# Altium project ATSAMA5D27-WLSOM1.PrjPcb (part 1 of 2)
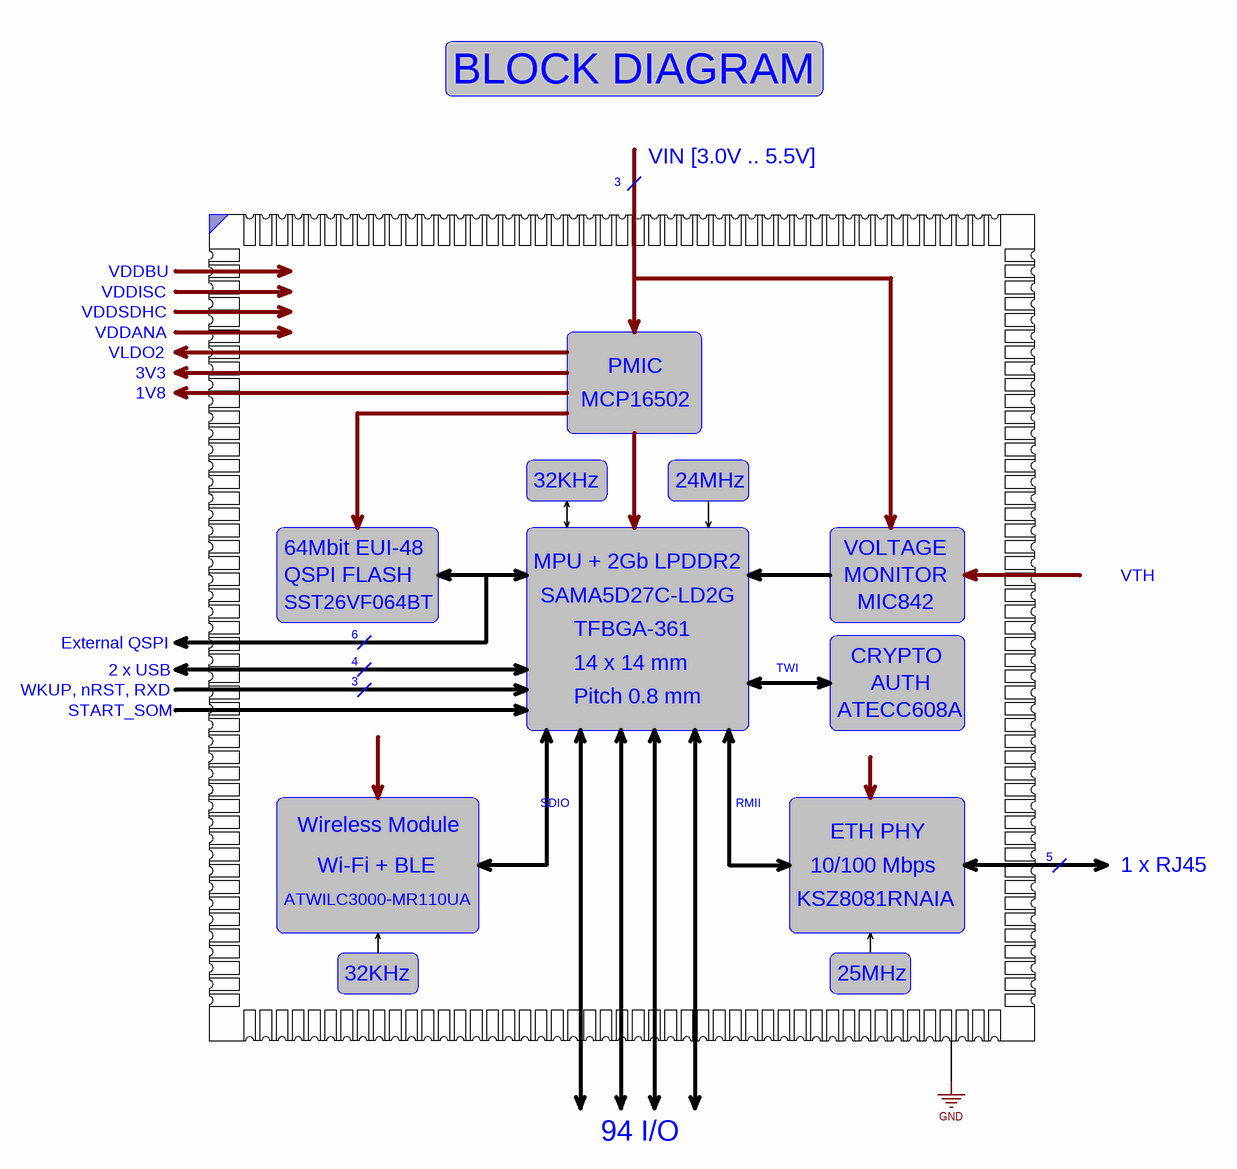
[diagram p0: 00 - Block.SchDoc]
ProjectBoardNumber: WLSOM1; ProjectDrawnBy: MS; ProjectEngineer: RC; ProjectPartNumber: ATSAMA5D27-WLSOM1; ProjectRevisionART: B; ProjectRevisionASSY: B; ProjectRevisionFAB: B; ProjectRevisionSCH: B; ProjectTitle: SAMA5D2 Wireless SOM
6 sheets, 202 parts. Net scope: flat (ports and power ports of the same name join across sheets).
Board file: ATSAMA5D27-WLSOM1.PcbDoc
Sheets:
  00 - Block.SchDoc
  01 - Power.SchDoc
  02 - MPU.SchDoc
  03 - Ethernet.SchDoc
  04 - WiFi-BLE-Flash.SchDoc
  05 - SOM-PIO.SchDoc

## Sheet 00 - Block.SchDoc
size B; CompanyName: Microchip Technology Inc.; Organization: Microchip Technology; Address1: 2355 West Chandler Blvd.; Address2: Chandler, AZ  85224; Address4: USA; SheetNumber: 1; SheetTotal: 6; SheetTitle: BLOCK DIAGRAM

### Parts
(Parts that share a designator on the sheet are numbered #1, #2 ... from top to bottom, then left to right.)
?#1  (no value)  (graphical)

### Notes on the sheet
- BLOCK DIAGRAM
- 3
- VIN [3.0V .. 5.5V]
- VDDBU
- VDDSDHC
- VDDANA
- VDDISC
- VLDO2
- 1V8
- 3V3
- MCP16502
- PMIC
- 32KHz
- 24MHz
- 64Mbit EUI-48
- VOLTAGE
- SST26VF064BT
- QSPI FLASH
- MPU + 2Gb LPDDR2
- SAMA5D27C-LD2G
- TFBGA-361
- MONITOR
- MIC842
- VTH
- WKUP, nRST, RXD
- External QSPI
- 2 x USB
- 4
- 6
- 14 x 14 mm
- TWI
- CRYPTO
- AUTH
- START_SOM
- Pitch 0.8 mm
- ATECC608A
- Wireless Module
- SDIO
- RMII
- ATWILC3000-MR110UA
- Wi-Fi + BLE
- KSZ8081RNAIA
- 10/100 Mbps
- ETH PHY
- 5
- 1 x RJ45
- 25MHz
- 94 I/O
- Labels drawn without touching a wire or pin: GND

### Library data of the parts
?#1 = Title Block B

## Sheet 01 - Power.SchDoc
size B; CompanyName: Microchip Technology Inc.; Organization: Microchip Technology; Address1: 2355 West Chandler Blvd.; Address2: Chandler, AZ  85224; Address4: USA; SheetNumber: 2; SheetTotal: 6; SheetTitle: Power Supply
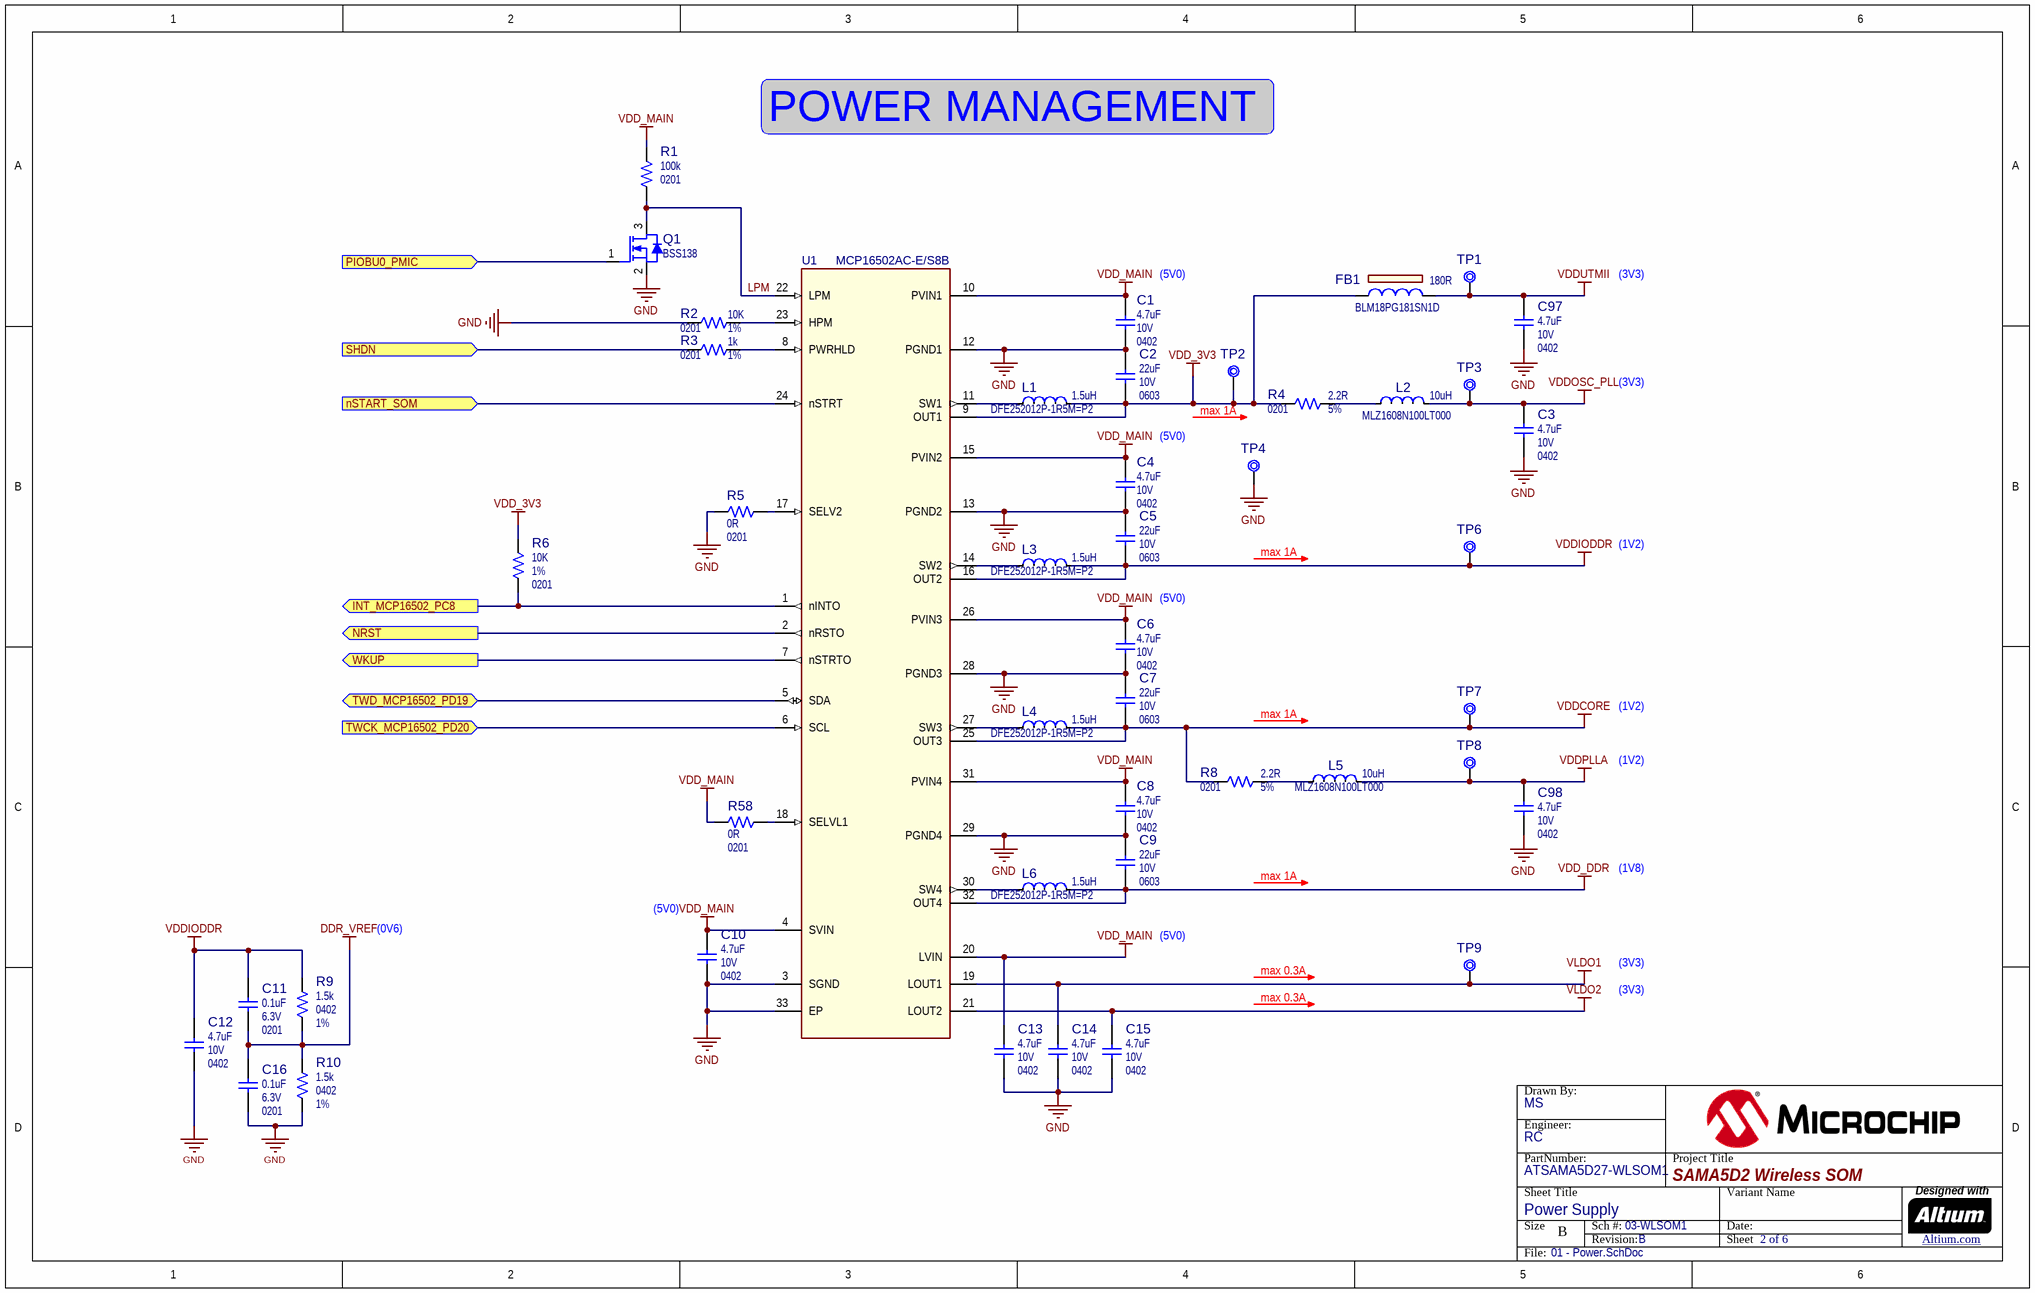
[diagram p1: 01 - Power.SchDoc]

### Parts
(Parts that share a designator on the sheet are numbered #1, #2 ... from top to bottom, then left to right.)
?#2  (no value)  (graphical)
C1  value 4.7uF  Voltage: 10V  Package: 0402  [CAP_C_0402]  (hidden comment: Capacitor NP)
C2  value 22uF  Voltage: 10V  Package: 0603  [CAP_C_0603]  (hidden comment: Capacitor NP)
C3  value 4.7uF  Voltage: 10V  Package: 0402  [CAP_C_0402]  (hidden comment: Capacitor NP)
C4  value 4.7uF  Voltage: 10V  Package: 0402  [CAP_C_0402]  (hidden comment: Capacitor NP)
C5  value 22uF  Voltage: 10V  Package: 0603  [CAP_C_0603]  (hidden comment: Capacitor NP)
C6  value 4.7uF  Voltage: 10V  Package: 0402  [CAP_C_0402]  (hidden comment: Capacitor NP)
C7  value 22uF  Voltage: 10V  Package: 0603  [CAP_C_0603]  (hidden comment: Capacitor NP)
C8  value 4.7uF  Voltage: 10V  Package: 0402  [CAP_C_0402]  (hidden comment: Capacitor NP)
C9  value 22uF  Voltage: 10V  Package: 0603  [CAP_C_0603]  (hidden comment: Capacitor NP)
C10  value 4.7uF  Voltage: 10V  Package: 0402  [CAP_C_0402]  (hidden comment: Capacitor NP)
C11  value 0.1uF  Voltage: 6.3V  Package: 0201  [CAP_C_0201]  (hidden comment: Capacitor NP)
C12  value 4.7uF  Voltage: 10V  Package: 0402  [CAP_C_0402]  (hidden comment: Capacitor NP)
C13  value 4.7uF  Voltage: 10V  Package: 0402  [CAP_C_0402]  (hidden comment: Capacitor NP)
C14  value 4.7uF  Voltage: 10V  Package: 0402  [CAP_C_0402]  (hidden comment: Capacitor NP)
C15  value 4.7uF  Voltage: 10V  Package: 0402  [CAP_C_0402]  (hidden comment: Capacitor NP)
C16  value 0.1uF  Voltage: 6.3V  Package: 0201  [CAP_C_0201]  (hidden comment: Capacitor NP)
C97  value 4.7uF  Voltage: 10V  Package: 0402  [CAP_C_0402]  (hidden comment: Capacitor NP)
C98  value 4.7uF  Voltage: 10V  Package: 0402  [CAP_C_0402]  (hidden comment: Capacitor NP)
FB1  value 180R  Manufacturer Part Number 1: BLM18PG181SN1D  [IND_C_0603]  (hidden comment: Ferrite Bead)
L1  value 1.5uH  Manufacturer Part Number 1: DFE252012P-1R5M=P2  [IND_C_1008]  (hidden comment: Inductor)
L2  value 10uH  Manufacturer Part Number 1: MLZ1608N100LT000  [IND_C_0603]  (hidden comment: Inductor)
L3  value 1.5uH  Manufacturer Part Number 1: DFE252012P-1R5M=P2  [IND_C_1008]  (hidden comment: Inductor)
L4  value 1.5uH  Manufacturer Part Number 1: DFE252012P-1R5M=P2  [IND_C_1008]  (hidden comment: Inductor)
L5  value 10uH  Manufacturer Part Number 1: MLZ1608N100LT000  [IND_C_0603]  (hidden comment: Inductor)
L6  value 1.5uH  Manufacturer Part Number 1: DFE252012P-1R5M=P2  [IND_C_1008]  (hidden comment: Inductor)
Q1  value BSS138  [SOT-23-3]  (hidden comment: Transistor MOS-N GSD)
R1  value 100k  Package: 0201  [RES_C_0201]  (hidden comment: Resistor)
R2  value 10K  Package: 0201  Tolerance: 1%  [RES_C_0201]  (hidden comment: Resistor)
R3  value 1k  Package: 0201  Tolerance: 1%  [RES_C_0201]  (hidden comment: Resistor)
R4  value 2.2R  Package: 0201  Tolerance: 5%  [RES_C_0201]  (hidden comment: Resistor)
R5  value 0R  Package: 0201  [RES_C_0201]  (hidden comment: Resistor)
R6  value 10K  Package: 0201  Tolerance: 1%  [RES_C_0201]  (hidden comment: Resistor)
R8  value 2.2R  Package: 0201  Tolerance: 5%  [RES_C_0201]  (hidden comment: Resistor)
R9  value 1.5k  Package: 0402  Tolerance: 1%  [RES_C_0402]  (hidden comment: Resistor)
R10  value 1.5k  Package: 0402  Tolerance: 1%  [RES_C_0402]  (hidden comment: Resistor)
R58  value 0R  Package: 0201  [RES_C_0201_NT]  (hidden comment: Resistor)  (net tie, no BOM)
TP1  Test Point No BOM  [TP_1mm_SMD]  (value not drawn)  (no BOM)
TP2  Test Point No BOM  [TP_1mm_SMD]  (value not drawn)  (no BOM)
TP3  Test Point No BOM  [TP_1mm_SMD]  (value not drawn)  (no BOM)
TP4  Test Point No BOM  [TP_1mm_SMD]  (value not drawn)  (no BOM)
TP6  Test Point No BOM  [TP_1mm_SMD]  (value not drawn)  (no BOM)
TP7  Test Point No BOM  [TP_1mm_SMD]  (value not drawn)  (no BOM)
TP8  Test Point No BOM  [TP_1mm_SMD]  (value not drawn)  (no BOM)
TP9  Test Point No BOM  [TP_1mm_SMD]  (value not drawn)  (no BOM)
U1  value MCP16502AC-E/S8B  [QFN-32_5X5_EP3.7X3.7]  (hidden comment: MCP16502 QFN-32)

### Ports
INT_MCP16502_PC8 (out), NRST (out), nSTART_SOM (in), PIOBU0_PMIC (in), SHDN (in), TWCK_MCP16502_PD20 (in), TWD_MCP16502_PD19 (bidir), WKUP (out)

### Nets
DDR_VREF: C11.1 C16.2 R9.1 R10.2
GND: C1.1 C2.2 C3.1 C4.1 C5.2 C6.1 C7.2 C8.1 C9.2 C10.1 C12.1 C13.1 C14.1 C15.1 C16.1 C97.1 C98.1 Q1.2(S) R2.2 R5.2 R10.1 TP4.1 U1.3(SGND) U1.12(PGND1) U1.13(PGND2) U1.28(PGND3) U1.29(PGND4) U1.33(EP)
VDD_3V3: C2.1 FB1.1 L1.2(F) R4.1 R6.2 TP2.1 U1.9(OUT1)
VDD_DDR: C9.1 L6.2(F) U1.32(OUT4)
VDD_MAIN: C1.2 C4.2 C6.2 C8.2 C10.2 C13.2 R1.2 R58.1 U1.4(SVIN) U1.10(PVIN1) U1.15(PVIN2) U1.20(LVIN) U1.26(PVIN3) U1.31(PVIN4)
VDDCORE: C7.1 L4.2(F) R8.1 TP7.1 U1.25(OUT3)
VDDIODDR: C5.1 C11.2 C12.2 L3.2(F) R9.2 TP6.1 U1.16(OUT2)
VDDOSC_PLL: C3.2 L2.2(F) TP3.1
VDDPLLA: C98.2 L5.2(F) TP8.1
VDDUTMII: C97.2 FB1.2 TP1.1
VLDO1: C14.2 TP9.1 U1.19(LOUT1)
VLDO2: C15.2 U1.21(LOUT2)
INT_MCP16502_PC8: R6.1 U1.1(nINTO) ; port INT_MCP16502_PC8
LPM: Q1.3(D) R1.1 U1.22(LPM)
NRST: U1.2(nRSTO) ; port NRST
nSTART_SOM: U1.24(nSTRT) ; port nSTART_SOM
PIOBU0_PMIC: Q1.1(G) ; port PIOBU0_PMIC
SHDN: R3.1 ; port SHDN
TWCK_MCP16502_PD20: U1.6(SCL) ; port TWCK_MCP16502_PD20
TWD_MCP16502_PD19: U1.5(SDA) ; port TWD_MCP16502_PD19
WKUP: U1.7(nSTRTO) ; port WKUP
NetL1_1: L1.1(S) U1.11(SW1)
NetL2_1: L2.1(S) R4.2
NetL3_1: L3.1(S) U1.14(SW2)
NetL4_1: L4.1(S) U1.27(SW3)
NetL5_1: L5.1(S) R8.2
NetL6_1: L6.1(S) U1.30(SW4)
NetR2_1: R2.1 U1.23(HPM)
NetR3_2: R3.2 U1.8(PWRHLD)
NetR5_1: R5.1 U1.17(SELV2)
NetR58_2: R58.2 U1.18(SELVL1)

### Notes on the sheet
- POWER MANAGEMENT
- (near C1) (5V0)
- (3V3)
- (near TP2) max 1A
- (5V0)
- max 1A
- (1V2)
- (near C10) (5V0)
- (1V8)
- (0V6)
- max 0.3A

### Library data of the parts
?#2 = Title Block B
C1 C3 C4 C6 C8 C10 C12-C15 C97 C98 = CAP1684: Capacitor; Manufacturer 1: TDK Corporation; Manufacturer Part Number 1: C1005X5R1A475K050BC; Description_: CAP CER 4.7uF 10V 10% X5R SMD 0402; Dev Tools Status: Production; Tolerance: 10%; Temperature Coeffcient: X5R; Type: Ceramic; Owner: Jesus Aviles; Populated: YES
C2 C5 C7 C9 = CAP1648: Capacitor; Manufacturer 1: TDK Corporation; Manufacturer Part Number 1: C1608X5R1A226M080AC; Description_: CAP CER 22uF 10V 20% X5R SMD 0603; Dev Tools Status: Production; Tolerance: 20%; Temperature Coeffcient: X5R; Type: Ceramic; Owner: Razvan Cristescu; Populated: YES
C11 C16 = CAP2003: Capacitor; Manufacturer 1: KEMET; Manufacturer Part Number 1: C0201C104K9PACTU; Description_: CAP CER 0.1uF 6.3V 10% X5R 0201; Dev Tools Status: Design; Tolerance: 10%; Temperature Coeffcient: X5R; Owner: Dragos Danaila; Populated: YES; ESR: 0.005R; Type: Ceramic
FB1 = IND1453: FERRITE 180R 1.5A SMD 0603; Manufacturer 1: Murata Electronics North America; Dev Tools Status: Production; Owner: Dragos Danaila; DCR: 0.09R; Test Frequency: 100MHz; Populated: YES
L1 L3 L4 L6 = IND1335: Manufacturer 1: Murata Electronics North America; Description_: INDUCTOR 1.5uH 3.5A 20% SMD 1008; Dev Tools Status: Design; Owner: Razvan Cristescu; DCR: 0.06R; RMS Current: 3.5A; Test Frequency: 1MHz; Populated: YES
L2 L5 = IND1213: Manufacturer 1: TDK Corporation; Description_: INDUCTOR 10uH 600mA 20% SMD 0603; Dev Tools Status: Design; Owner: Jamus Griego; Populated: YES; DCR: 0.6R; RMS Current: 300mA; Saturation Current: 60mA; Test Frequency: 2MHz
Q1 = TRA1147: Transistor MOS; Manufacturer 1: Fairchild; Description_: TRANS FET N-CH BSS138 50V 220mA 360mW SOT-23; Dev Tools Status: Production; Type: FET; Current: 220mA; Drain to Source Voltage: 50V; Gate to Source Voltage: 1.3V; Power: 360mW; Owner: Razvan Cristescu; Populated: YES
R1 = RES1582: Manufacturer 1: Panasonic Electronic Components; Manufacturer Part Number 1: ERJ-1GEF1003C; Tolerance: 1%; Description_: RES TKF 100k 1% 1/20W SMD 0201; Dev Tools Status: Design; Voltage: 15V; Temperature Coeffcient: 200ppm/C; Power: 1/20W; Owner: Gabor Bihari; Populated: YES
R2 R6 = RSMT1252: Manufacturer 1: Yageo; Manufacturer Part Number 1: RC0201FR-0710KL; Description_: RES TKF 10K 1% 1/20W SMD 0201; Dev Tools Status: Design; Voltage: 25V; Temperature Coeffcient: 200pm/C; Power: 1/20W; Owner: Dragos Danaila; Populated: YES
R3 = RES1588: Manufacturer 1: Panasonic Electronic Components; Manufacturer Part Number 1: ERJ-1GEF1001C; Description_: RES TKF 1k 1% 1/20W SMD 0201; Dev Tools Status: Design; Voltage: 25V; Power: 1/20W; Owner: Gabor Bihari; Populated: YES
R4 R8 = RSMT1253: Manufacturer 1: Yageo; Manufacturer Part Number 1: RC0201JR-072R2L; Description_: RES TKF 2.2R 5% 1/20W SMD 0201; Dev Tools Status: Design; Voltage: 25V; Temperature Coeffcient: -100/+350 ppm/C; Power: 1/20W; Owner: Dragos Danaila; Populated: YES
R5 = RSMT1240: Manufacturer 1: Panasonic Electronic Components; Manufacturer Part Number 1: ERJ-1GN0R00C; Description_: RES TKF 0R 1/20W SMD 0201; Dev Tools Status: Design; Voltage: 50V; Current: 0.5A; Power: 1/20W; Owner: Dragos Danaila; Populated: YES
R9 R10 = RES2022: Manufacturer 1: Yageo; Manufacturer Part Number 1: RC0402FR-071K5L; Description_: RES TKF 1.5K 1% 1/16W SMD 0402; Dev Tools Status: Design; Temperature Coeffcient: 100ppm/°C; Power: 1/16W; Owner: Ilie Galan; Populated: YES
R58 = RSMT1240: Manufacturer 1: Panasonic Electronic Components; Manufacturer Part Number 1: ERJ-1GN0R00C; Description_: RES TKF 0R 1/20W SMD 0201; Dev Tools Status: Design; Voltage: 50V; Current: 0.5A; Power: 1/20W; Owner: Dragos Danaila; Populated: DNP
TP1-TP4 TP6-TP9 = CON1759: Test Point; Value: TP PAD PCB 1mm; Description_: CON TP PAD PCB 1mm SMD; Dev Tools Status: Design; Owner: Cristian Papuc; Populated: YES
U1 = MIC8644: Manufacturer 1: Microchip Technology; Description_: MCHP ANALOG PMIC SWITCHER Buck ADJ MCP16502AC-E/S8B QFN-32; Dev Tools Status: Design; Owner: Dragos Danaila; Populated: YES

## Sheet 02 - MPU.SchDoc
size A3; CompanyName: Microchip Technology Inc.; Organization: Microchip Technology; Address1: 2355 West Chandler Blvd.; Address2: Chandler, AZ  85224; Address4: USA; SheetNumber: 3; SheetTotal: 6; SheetTitle: SAMA5D2-LPDDR2-SIP
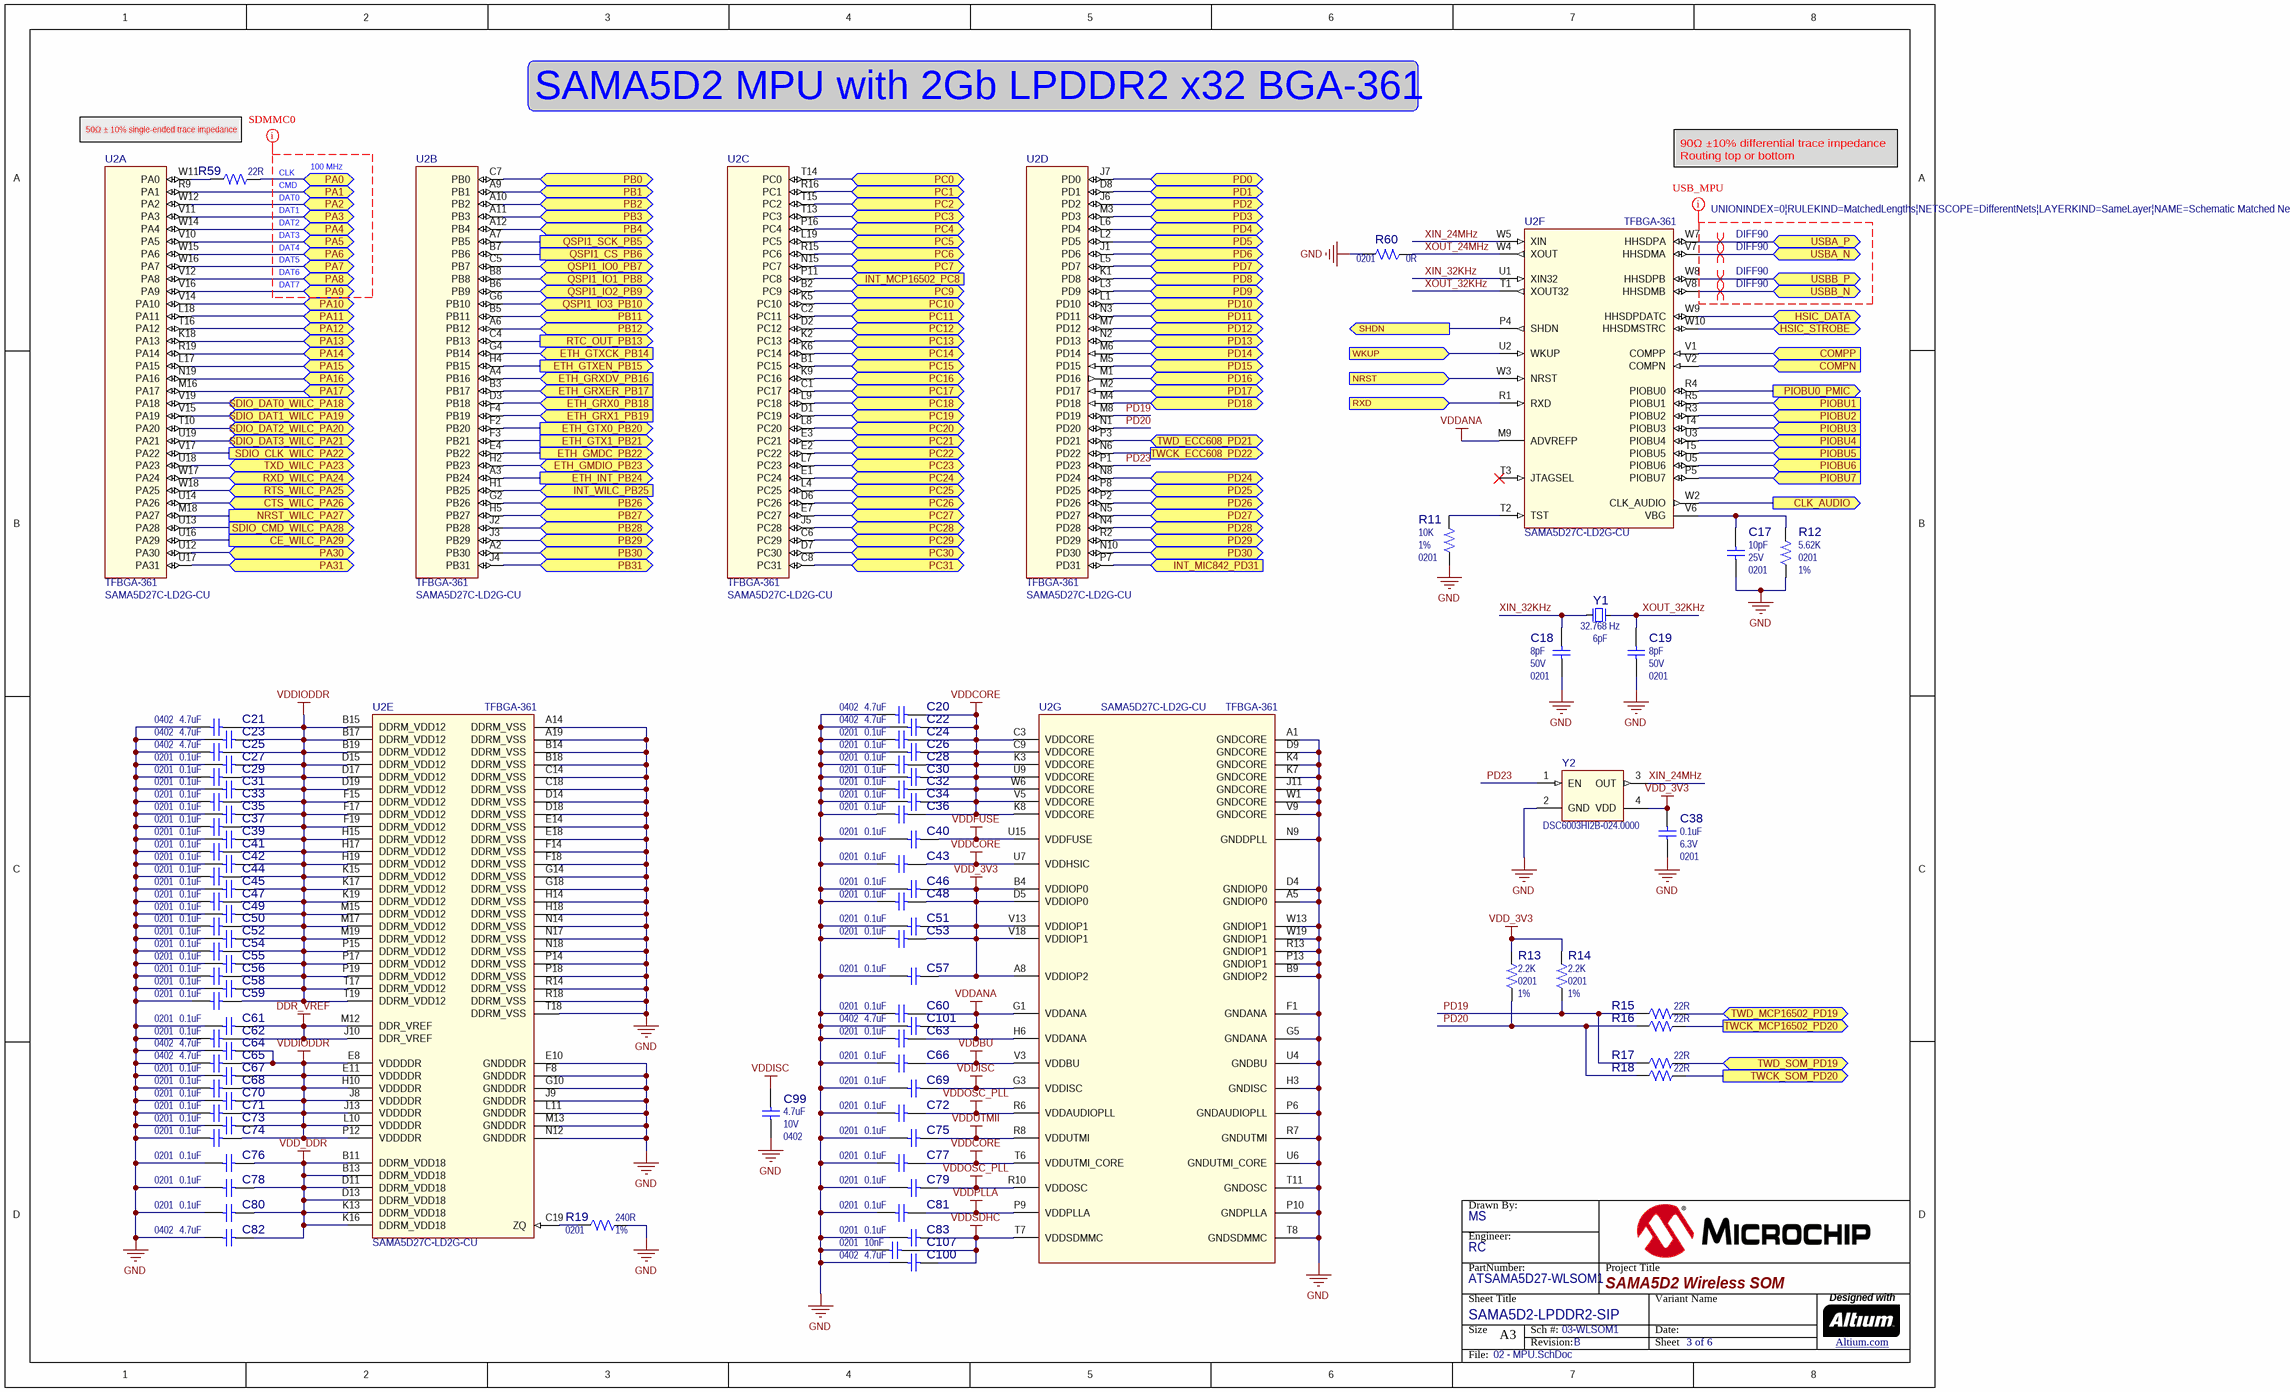
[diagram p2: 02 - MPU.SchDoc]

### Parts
(Parts that share a designator on the sheet are numbered #1, #2 ... from top to bottom, then left to right.)
?#3  (no value)  (graphical)
C17  value 10pF  Voltage: 25V  Package: 0201  [CAP_C_0201]  (hidden comment: Capacitor NP)
C18  value 8pF  Voltage: 50V  Package: 0201  [CAP_C_0201]  (hidden comment: Capacitor NP)
C19  value 8pF  Voltage: 50V  Package: 0201  [CAP_C_0201]  (hidden comment: Capacitor NP)
C20  value 4.7uF  Package: 0402  [CAP_C_0402]  (hidden comment: Capacitor NP)
C21  value 4.7uF  Package: 0402  [CAP_C_0402]  (hidden comment: Capacitor NP)
C22  value 4.7uF  Package: 0402  [CAP_C_0402]  (hidden comment: Capacitor NP)
C23  value 4.7uF  Package: 0402  [CAP_C_0402]  (hidden comment: Capacitor NP)
C24  value 0.1uF  Package: 0201  [CAP_C_0201]  (hidden comment: Capacitor NP)
C25  value 4.7uF  Package: 0402  [CAP_C_0402]  (hidden comment: Capacitor NP)
C26  value 0.1uF  Package: 0201  [CAP_C_0201]  (hidden comment: Capacitor NP)
C27  value 0.1uF  Package: 0201  [CAP_C_0201]  (hidden comment: Capacitor NP)
C28  value 0.1uF  Package: 0201  [CAP_C_0201]  (hidden comment: Capacitor NP)
C29  value 0.1uF  Package: 0201  [CAP_C_0201]  (hidden comment: Capacitor NP)
C30  value 0.1uF  Package: 0201  [CAP_C_0201]  (hidden comment: Capacitor NP)
C31  value 0.1uF  Package: 0201  [CAP_C_0201]  (hidden comment: Capacitor NP)
C32  value 0.1uF  Package: 0201  [CAP_C_0201]  (hidden comment: Capacitor NP)
C33  value 0.1uF  Package: 0201  [CAP_C_0201]  (hidden comment: Capacitor NP)
C34  value 0.1uF  Package: 0201  [CAP_C_0201]  (hidden comment: Capacitor NP)
C35  value 0.1uF  Package: 0201  [CAP_C_0201]  (hidden comment: Capacitor NP)
C36  value 0.1uF  Package: 0201  [CAP_C_0201]  (hidden comment: Capacitor NP)
C37  value 0.1uF  Package: 0201  [CAP_C_0201]  (hidden comment: Capacitor NP)
C38  value 0.1uF  Voltage: 6.3V  Package: 0201  [CAP_C_0201]  (hidden comment: Capacitor NP)
C39  value 0.1uF  Package: 0201  [CAP_C_0201]  (hidden comment: Capacitor NP)
C40  value 0.1uF  Package: 0201  [CAP_C_0201]  (hidden comment: Capacitor NP)
C41  value 0.1uF  Package: 0201  [CAP_C_0201]  (hidden comment: Capacitor NP)
C42  value 0.1uF  Package: 0201  [CAP_C_0201]  (hidden comment: Capacitor NP)
C43  value 0.1uF  Package: 0201  [CAP_C_0201]  (hidden comment: Capacitor NP)
C44  value 0.1uF  Package: 0201  [CAP_C_0201]  (hidden comment: Capacitor NP)
C45  value 0.1uF  Package: 0201  [CAP_C_0201]  (hidden comment: Capacitor NP)
C46  value 0.1uF  Package: 0201  [CAP_C_0201]  (hidden comment: Capacitor NP)
C47  value 0.1uF  Package: 0201  [CAP_C_0201]  (hidden comment: Capacitor NP)
C48  value 0.1uF  Package: 0201  [CAP_C_0201]  (hidden comment: Capacitor NP)
C49  value 0.1uF  Package: 0201  [CAP_C_0201]  (hidden comment: Capacitor NP)
C50  value 0.1uF  Package: 0201  [CAP_C_0201]  (hidden comment: Capacitor NP)
C51  value 0.1uF  Package: 0201  [CAP_C_0201]  (hidden comment: Capacitor NP)
C52  value 0.1uF  Package: 0201  [CAP_C_0201]  (hidden comment: Capacitor NP)
C53  value 0.1uF  Package: 0201  [CAP_C_0201]  (hidden comment: Capacitor NP)
C54  value 0.1uF  Package: 0201  [CAP_C_0201]  (hidden comment: Capacitor NP)
C55  value 0.1uF  Package: 0201  [CAP_C_0201]  (hidden comment: Capacitor NP)
C56  value 0.1uF  Package: 0201  [CAP_C_0201]  (hidden comment: Capacitor NP)
C57  value 0.1uF  Package: 0201  [CAP_C_0201]  (hidden comment: Capacitor NP)
C58  value 0.1uF  Package: 0201  [CAP_C_0201]  (hidden comment: Capacitor NP)
C59  value 0.1uF  Package: 0201  [CAP_C_0201]  (hidden comment: Capacitor NP)
C60  value 0.1uF  Package: 0201  [CAP_C_0201]  (hidden comment: Capacitor NP)
C61  value 0.1uF  Package: 0201  [CAP_C_0201]  (hidden comment: Capacitor NP)
C62  value 0.1uF  Package: 0201  [CAP_C_0201]  (hidden comment: Capacitor NP)
C63  value 0.1uF  Package: 0201  [CAP_C_0201]  (hidden comment: Capacitor NP)
C64  value 4.7uF  Package: 0402  [CAP_C_0402]  (hidden comment: Capacitor NP)
C65  value 4.7uF  Package: 0402  [CAP_C_0402]  (hidden comment: Capacitor NP)
C66  value 0.1uF  Package: 0201  [CAP_C_0201]  (hidden comment: Capacitor NP)
C67  value 0.1uF  Package: 0201  [CAP_C_0201]  (hidden comment: Capacitor NP)
C68  value 0.1uF  Package: 0201  [CAP_C_0201]  (hidden comment: Capacitor NP)
C69  value 0.1uF  Package: 0201  [CAP_C_0201]  (hidden comment: Capacitor NP)
C70  value 0.1uF  Package: 0201  [CAP_C_0201]  (hidden comment: Capacitor NP)
C71  value 0.1uF  Package: 0201  [CAP_C_0201]  (hidden comment: Capacitor NP)
C72  value 0.1uF  Package: 0201  [CAP_C_0201]  (hidden comment: Capacitor NP)
C73  value 0.1uF  Package: 0201  [CAP_C_0201]  (hidden comment: Capacitor NP)
C74  value 0.1uF  Package: 0201  [CAP_C_0201]  (hidden comment: Capacitor NP)
C75  value 0.1uF  Package: 0201  [CAP_C_0201]  (hidden comment: Capacitor NP)
C76  value 0.1uF  Package: 0201  [CAP_C_0201]  (hidden comment: Capacitor NP)
C77  value 0.1uF  Package: 0201  [CAP_C_0201]  (hidden comment: Capacitor NP)
C78  value 0.1uF  Package: 0201  [CAP_C_0201]  (hidden comment: Capacitor NP)
C79  value 0.1uF  Package: 0201  [CAP_C_0201]  (hidden comment: Capacitor NP)
C80  value 0.1uF  Package: 0201  [CAP_C_0201]  (hidden comment: Capacitor NP)
C81  value 0.1uF  Package: 0201  [CAP_C_0201]  (hidden comment: Capacitor NP)
C82  value 4.7uF  Package: 0402  [CAP_C_0402]  (hidden comment: Capacitor NP)
C83  value 0.1uF  Package: 0201  [CAP_C_0201]  (hidden comment: Capacitor NP)
C99  value 4.7uF  Voltage: 10V  Package: 0402  [CAP_C_0402]  (hidden comment: Capacitor NP)
C100  value 4.7uF  Package: 0402  [CAP_C_0402]  (hidden comment: Capacitor NP)
C101  value 4.7uF  Package: 0402  [CAP_C_0402]  (hidden comment: Capacitor NP)
C107  value 10nF  Package: 0201  [CAP_C_0201]  (hidden comment: Capacitor NP)
R11  value 10K  Package: 0201  Tolerance: 1%  [RES_C_0201]  (hidden comment: Resistor)
R12  value 5.62K  Package: 0201  Tolerance: 1%  [RES_C_0201]  (hidden comment: Resistor)
R13  value 2.2K  Package: 0201  Tolerance: 1%  [RES_C_0201]  (hidden comment: Resistor)
R14  value 2.2K  Package: 0201  Tolerance: 1%  [RES_C_0201]  (hidden comment: Resistor)
R15  value 22R  [RES_C_0201]  (hidden comment: Resistor)
R16  value 22R  [RES_C_0201]  (hidden comment: Resistor)
R17  value 22R  [RES_C_0201]  (hidden comment: Resistor)
R18  value 22R  [RES_C_0201]  (hidden comment: Resistor)
R19  value 240R  Package: 0201  Tolerance: 1%  [RES_C_0201]  (hidden comment: Resistor)
R59  value 22R  [RES_C_0201]  (hidden comment: Resistor)
R60  value 0R  Package: 0201  [RES_C_0201]  (hidden comment: Resistor)
U2  SAMA5D27C-LD2G-CU  PackageType: TFBGA-361  [TFBGA-361-16X16]  (parts A,B,C,D,E,F,G of 7)
Y1  value 32.768 Hz  Load Capacitance: 6pF  [CRYSTAL_NX2012SA]  (hidden comment: Crystal 2 Pins)
Y2  Manufacturer Part Number 1: DSC6003HI2B-024.0000  [DFN-4_VFLGA_1.6 X 1.2]  (hidden comment: OSCILLATOR 4 Pins)

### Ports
CE_WILC_PA29 (out), CLK_AUDIO (out), COMPN (in), COMPP (in), CTS_WILC_PA26 (bidir), ETH_GMDC_PB22 (out), ETH_GMDIO_PB23 (bidir), ETH_GRX0_PB18 (in), ETH_GRX1_PB19 (in), ETH_GRXDV_PB16 (in), ETH_GRXER_PB17 (in), ETH_GTX0_PB20 (out), ETH_GTX1_PB21 (out), ETH_GTXCK_PB14 (in), ETH_GTXEN_PB15 (out), ETH_INT_PB24 (out), HSIC_DATA (bidir), HSIC_STROBE (bidir), INT_MCP16502_PC8 (in), INT_MIC842_PD31 (in), INT_WILC_PB25 (in), NRST (in), NRST_WILC_PA27 (out), PA0 (bidir), PA1 (bidir), PA2 (bidir), PA3 (bidir), PA4 (bidir), PA5 (bidir), PA6 (bidir), PA7 (bidir), PA8 (bidir), PA9 (bidir), PA10 (bidir), PA11 (bidir), PA12 (bidir), PA13 (bidir), PA14 (bidir), PA15 (bidir), PA16 (bidir), PA17 (bidir), PA30 (bidir), PA31 (bidir), PB0 (bidir), PB1 (bidir), PB2 (bidir), PB3 (bidir), PB4 (bidir), PB11 (bidir), PB12 (bidir), PB26 (bidir), PB27 (bidir), PB28 (bidir), PB29 (bidir), PB30 (bidir), PB31 (bidir), PC0 (bidir), PC1 (bidir), PC2 (bidir), PC3 (bidir), PC4 (bidir), PC5 (bidir), PC6 (bidir), PC7 (bidir), PC9 (bidir), PC10 (bidir), PC11 (bidir), PC12 (bidir), PC13 (bidir), PC14 (bidir), PC15 (bidir), PC16 (bidir), PC17 (bidir), PC18 (bidir), PC19 (bidir), PC20 (bidir), PC21 (bidir), PC22 (bidir), PC23 (bidir), PC24 (bidir), PC25 (bidir), PC26 (bidir), PC27 (bidir), PC28 (bidir), PC29 (bidir), PC30 (bidir), PC31 (bidir), PD0 (bidir), PD1 (bidir), PD2 (bidir), PD3 (bidir), PD4 (bidir), PD5 (bidir), PD6 (bidir), PD7 (bidir), PD8 (bidir), PD9 (bidir), PD10 (bidir), PD11 (bidir), PD12 (bidir), PD13 (bidir), PD14 (bidir), PD15 (bidir), PD16 (bidir), PD17 (bidir), PD18 (bidir), PD24 (bidir), PD25 (bidir), PD26 (bidir), PD27 (bidir), PD28 (bidir), PD29 (bidir), PD30 (bidir), PIOBU0_PMIC (out), PIOBU1 (in), PIOBU2 (in), PIOBU3 (in), PIOBU4 (in), PIOBU5 (in), PIOBU6 (in), PIOBU7 (in), QSPI1_CS_PB6 (out), QSPI1_IO0_PB7 (bidir), QSPI1_IO1_PB8 (bidir), QSPI1_IO2_PB9 (bidir), QSPI1_IO3_PB10 (bidir), QSPI1_SCK_PB5 (out), RTC_OUT_PB13 (out), RTS_WILC_PA25 (bidir), RXD (in), RXD_WILC_PA24 (bidir), SDIO_CLK_WILC_PA22 (out), SDIO_CMD_WILC_PA28 (out), SDIO_DAT0_WILC_PA18 (bidir), SDIO_DAT1_WILC_PA19 (bidir), SDIO_DAT2_WILC_PA20 (bidir), SDIO_DAT3_WILC_PA21 (bidir), SHDN (out), TWCK_ECC608_PD22 (out), TWCK_MCP16502_PD20 (out), TWCK_SOM_PD20 (out), TWD_ECC608_PD21 (bidir), TWD_MCP16502_PD19 (bidir), TWD_SOM_PD19 (bidir), TXD_WILC_PA23 (bidir), USBA_N (bidir), USBA_P (bidir), USBB_N (bidir), USBB_P (bidir), WKUP (in)

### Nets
DDR_VREF: C61.1 C62.1 U2.J10(DDR_VREF) U2.M12(DDR_VREF)
GND: C17.1 C18.1 C19.1 C20.2 C21.2 C22.2 C23.2 C24.2 C25.2 C26.2 C27.2 C28.2 C29.2 C30.2 C31.2 C32.2 C33.2 C34.2 C35.2 C36.2 C37.2 C38.1 C39.2 C40.2 C41.2 C42.2 C43.2 C44.2 C45.2 C46.2 C47.2 C48.2 C49.2 C50.2 C51.2 C52.2 C53.2 C54.2 C55.2 C56.2 C57.2 C58.2 C59.2 C60.2 C61.2 C62.2 C63.2 C64.2 C65.2 C66.2 C67.2 C68.2 C69.2 C70.2 C71.2 C72.2 C73.2 C74.2 C75.2 C76.2 C77.2 C78.2 C79.2 C80.2 C81.2 C82.2 C83.2 C99.1 C100.2 C101.2 C107.2 R11.1 R12.1 R19.2 R60.2 U2.A1(GNDCORE) U2.A5(GNDIOP0) U2.A14(DDRM_VSS) U2.A19(DDRM_VSS) U2.B9(GNDIOP2) U2.B14(DDRM_VSS) U2.B18(DDRM_VSS) U2.C14(DDRM_VSS) U2.C18(DDRM_VSS) U2.D4(GNDIOP0) U2.D9(GNDCORE) U2.D14(DDRM_VSS) U2.D18(DDRM_VSS) U2.E10(GNDDDR) U2.E14(DDRM_VSS) U2.E18(DDRM_VSS) U2.F1(GNDANA) U2.F8(GNDDDR) U2.F14(DDRM_VSS) U2.F18(DDRM_VSS) U2.G5(GNDANA) U2.G10(GNDDDR) U2.G14(DDRM_VSS) U2.G18(DDRM_VSS) U2.H3(GNDISC) U2.H14(DDRM_VSS) U2.H18(DDRM_VSS) U2.J9(GNDDDR) U2.J11(GNDCORE) U2.K4(GNDCORE) U2.K7(GNDCORE) U2.L11(GNDDDR) U2.M13(GNDDDR) U2.N9(GNDDPLL) U2.N12(GNDDDR) U2.N14(DDRM_VSS) U2.N17(DDRM_VSS) U2.N18(DDRM_VSS) U2.P6(GNDAUDIOPLL) U2.P10(GNDPLLA) U2.P13(GNDIOP1) U2.P14(DDRM_VSS) U2.P18(DDRM_VSS) U2.R7(GNDUTMI) U2.R13(GNDIOP1) U2.R14(DDRM_VSS) U2.R18(DDRM_VSS) U2.T8(GNDSDMMC) U2.T11(GNDOSC) U2.T18(DDRM_VSS) U2.U4(GNDBU) U2.U6(GNDUTMI_CORE) U2.V9(GNDCORE) U2.W1(GNDCORE) U2.W13(GNDIOP1) U2.W19(GNDIOP1) Y2.2(GND)
VDD_3V3: C38.2 C46.1 C48.1 C51.1 C53.1 C57.1 R13.2 R14.2 U2.A8(VDDIOP2) U2.B4(VDDIOP0) U2.D5(VDDIOP0) U2.V13(VDDIOP1) U2.V18(VDDIOP1) Y2.4(VDD)
VDD_DDR: C76.1 C78.1 C80.1 C82.1 U2.B11(DDRM_VDD18) U2.B13(DDRM_VDD18) U2.D11(DDRM_VDD18) U2.D13(DDRM_VDD18) U2.K13(DDRM_VDD18) U2.K16(DDRM_VDD18)
VDDANA: C60.1 C63.1 C101.1 U2.G1(VDDANA) U2.H6(VDDANA) U2.M9(ADVREFP)
VDDBU: C66.1 U2.V3(VDDBU)
VDDCORE: C20.1 C22.1 C24.1 C26.1 C28.1 C30.1 C32.1 C34.1 C36.1 C43.1 C77.1 U2.C3(VDDCORE) U2.C9(VDDCORE) U2.K3(VDDCORE) U2.K8(VDDCORE) U2.T6(VDDUTMI_CORE) U2.U7(VDDHSIC) U2.U9(VDDCORE) U2.V5(VDDCORE) U2.W6(VDDCORE)
VDDFUSE: C40.1 U2.U15(VDDFUSE)
VDDIODDR: C21.1 C23.1 C25.1 C27.1 C29.1 C31.1 C33.1 C35.1 C37.1 C39.1 C41.1 C42.1 C44.1 C45.1 C47.1 C49.1 C50.1 C52.1 C54.1 C55.1 C56.1 C58.1 C59.1 C64.1 C65.1 C67.1 C68.1 C70.1 C71.1 C73.1 C74.1 U2.B15(DDRM_VDD12) U2.B17(DDRM_VDD12) U2.B19(DDRM_VDD12) U2.D15(DDRM_VDD12) U2.D17(DDRM_VDD12) U2.D19(DDRM_VDD12) U2.E8(VDDDDR) U2.E11(VDDDDR) U2.F15(DDRM_VDD12) U2.F17(DDRM_VDD12) U2.F19(DDRM_VDD12) U2.H10(VDDDDR) U2.H15(DDRM_VDD12) U2.H17(DDRM_VDD12) U2.H19(DDRM_VDD12) U2.J8(VDDDDR) U2.J13(VDDDDR) U2.K15(DDRM_VDD12) U2.K17(DDRM_VDD12) U2.K19(DDRM_VDD12) U2.L10(VDDDDR) U2.M15(DDRM_VDD12) U2.M17(DDRM_VDD12) U2.M19(DDRM_VDD12) U2.P12(VDDDDR) U2.P15(DDRM_VDD12) U2.P17(DDRM_VDD12) U2.P19(DDRM_VDD12) U2.T17(DDRM_VDD12) U2.T19(DDRM_VDD12)
VDDISC: C69.1 C99.2 U2.G3(VDDISC)
VDDOSC_PLL: C72.1 C79.1 U2.R6(VDDAUDIOPLL) U2.R10(VDDOSC)
VDDPLLA: C81.1 U2.P9(VDDPLLA)
VDDSDHC: C83.1 C100.1 C107.1 U2.T7(VDDSDMMC)
VDDUTMII: C75.1 U2.R8(VDDUTMI)
CE_WILC_PA29: U2.U16(PA29) ; port CE_WILC_PA29
CLK_AUDIO: U2.W2(CLK_AUDIO) ; port CLK_AUDIO
COMPN: U2.V2(COMPN) ; port COMPN
COMPP: U2.V1(COMPP) ; port COMPP
CTS_WILC_PA26: U2.U14(PA26) ; port CTS_WILC_PA26
ETH_GMDC_PB22: U2.E4(PB22) ; port ETH_GMDC_PB22
ETH_GMDIO_PB23: U2.H2(PB23) ; port ETH_GMDIO_PB23
ETH_GRX0_PB18: U2.D3(PB18) ; port ETH_GRX0_PB18
ETH_GRX1_PB19: U2.F4(PB19) ; port ETH_GRX1_PB19
ETH_GRXDV_PB16: U2.A4(PB16) ; port ETH_GRXDV_PB16
ETH_GRXER_PB17: U2.B3(PB17) ; port ETH_GRXER_PB17
ETH_GTX0_PB20: U2.F2(PB20) ; port ETH_GTX0_PB20
ETH_GTX1_PB21: U2.F3(PB21) ; port ETH_GTX1_PB21
ETH_GTXCK_PB14: U2.G4(PB14) ; port ETH_GTXCK_PB14
ETH_GTXEN_PB15: U2.H4(PB15) ; port ETH_GTXEN_PB15
ETH_INT_PB24: U2.A3(PB24) ; port ETH_INT_PB24
HSIC_DATA: U2.W9(HHSDPDATC) ; port HSIC_DATA
HSIC_STROBE: U2.W10(HHSDMSTRC) ; port HSIC_STROBE
INT_MCP16502_PC8: U2.P11(PC8) ; port INT_MCP16502_PC8
INT_MIC842_PD31: U2.P7(PD31) ; port INT_MIC842_PD31
INT_WILC_PB25: U2.H1(PB25) ; port INT_WILC_PB25
NRST: U2.W3(NRST) ; port NRST
NRST_WILC_PA27: U2.M18(PA27) ; port NRST_WILC_PA27
PA0: R59.2 ; port PA0
PA1: U2.R9(PA1) ; port PA1
PA2: U2.W12(PA2) ; port PA2
PA3: U2.V11(PA3) ; port PA3
PA4: U2.W14(PA4) ; port PA4
PA5: U2.V10(PA5) ; port PA5
PA6: U2.W15(PA6) ; port PA6
PA7: U2.W16(PA7) ; port PA7
PA8: U2.V12(PA8) ; port PA8
PA9: U2.V16(PA9) ; port PA9
PA10: U2.V14(PA10) ; port PA10
PA11: U2.L18(PA11) ; port PA11
PA12: U2.T16(PA12) ; port PA12
PA13: U2.K18(PA13) ; port PA13
PA14: U2.R19(PA14) ; port PA14
PA15: U2.L17(PA15) ; port PA15
PA16: U2.N19(PA16) ; port PA16
PA17: U2.M16(PA17) ; port PA17
PA30: U2.U12(PA30) ; port PA30
PA31: U2.U17(PA31) ; port PA31
PB0: U2.C7(PB0) ; port PB0
PB1: U2.A9(PB1) ; port PB1
PB2: U2.A10(PB2) ; port PB2
PB3: U2.A11(PB3) ; port PB3
PB4: U2.A12(PB4) ; port PB4
PB11: U2.B5(PB11) ; port PB11
PB12: U2.A6(PB12) ; port PB12
PB26: U2.G2(PB26) ; port PB26
PB27: U2.H5(PB27) ; port PB27
PB28: U2.J2(PB28) ; port PB28
PB29: U2.J3(PB29) ; port PB29
PB30: U2.A2(PB30) ; port PB30
PB31: U2.J4(PB31) ; port PB31
PC0: U2.T14(PC0) ; port PC0
PC1: U2.R16(PC1) ; port PC1
PC2: U2.T15(PC2) ; port PC2
PC3: U2.T13(PC3) ; port PC3
PC4: U2.P16(PC4) ; port PC4
PC5: U2.L19(PC5) ; port PC5
PC6: U2.R15(PC6) ; port PC6
PC7: U2.N15(PC7) ; port PC7
PC9: U2.B2(PC9) ; port PC9
PC10: U2.K5(PC10) ; port PC10
PC11: U2.C2(PC11) ; port PC11
PC12: U2.D2(PC12) ; port PC12
PC13: U2.K2(PC13) ; port PC13
PC14: U2.K6(PC14) ; port PC14
PC15: U2.B1(PC15) ; port PC15
PC16: U2.K9(PC16) ; port PC16
PC17: U2.C1(PC17) ; port PC17
PC18: U2.L9(PC18) ; port PC18
PC19: U2.D1(PC19) ; port PC19
PC20: U2.L8(PC20) ; port PC20
PC21: U2.E3(PC21) ; port PC21
PC22: U2.E2(PC22) ; port PC22
PC23: U2.L7(PC23) ; port PC23
PC24: U2.E1(PC24) ; port PC24
PC25: U2.L4(PC25) ; port PC25
PC26: U2.D6(PC26) ; port PC26
PC27: U2.E7(PC27) ; port PC27
PC28: U2.J5(PC28) ; port PC28
PC29: U2.C6(PC29) ; port PC29
PC30: U2.D7(PC30) ; port PC30
PC31: U2.C8(PC31) ; port PC31
PD0: U2.J7(PD0) ; port PD0
PD1: U2.D8(PD1) ; port PD1
PD2: U2.J6(PD2) ; port PD2
PD3: U2.M3(PD3) ; port PD3
PD4: U2.L6(PD4) ; port PD4
PD5: U2.L2(PD5) ; port PD5
PD6: U2.J1(PD6) ; port PD6
PD7: U2.L5(PD7) ; port PD7
PD8: U2.K1(PD8) ; port PD8
PD9: U2.L3(PD9) ; port PD9
PD10: U2.L1(PD10) ; port PD10
PD11: U2.N3(PD11) ; port PD11
PD12: U2.M7(PD12) ; port PD12
PD13: U2.N2(PD13) ; port PD13
PD14: U2.M6(PD14) ; port PD14
PD15: U2.M5(PD15) ; port PD15
PD16: U2.M1(PD16) ; port PD16
PD17: U2.M2(PD17) ; port PD17
PD18: U2.M4(PD18) ; port PD18
PD19: R14.1 R15.1 R17.1 U2.M8(PD19)
PD20: R13.1 R16.1 R18.1 U2.N1(PD20)
PD23: U2.P1(PD23) Y2.1(EN)
PD24: U2.N8(PD24) ; port PD24
PD25: U2.P8(PD25) ; port PD25
PD26: U2.P2(PD26) ; port PD26
PD27: U2.N5(PD27) ; port PD27
PD28: U2.N4(PD28) ; port PD28
PD29: U2.R2(PD29) ; port PD29
PD30: U2.N10(PD30) ; port PD30
PIOBU0_PMIC: U2.R4(PIOBU0) ; port PIOBU0_PMIC
PIOBU1: U2.R5(PIOBU1) ; port PIOBU1
PIOBU2: U2.R3(PIOBU2) ; port PIOBU2
PIOBU3: U2.T4(PIOBU3) ; port PIOBU3
PIOBU4: U2.U3(PIOBU4) ; port PIOBU4
PIOBU5: U2.T5(PIOBU5) ; port PIOBU5
PIOBU6: U2.U5(PIOBU6) ; port PIOBU6
PIOBU7: U2.P5(PIOBU7) ; port PIOBU7
QSPI1_CS_PB6: U2.B7(PB6) ; port QSPI1_CS_PB6
QSPI1_IO0_PB7: U2.C5(PB7) ; port QSPI1_IO0_PB7
QSPI1_IO1_PB8: U2.B8(PB8) ; port QSPI1_IO1_PB8
QSPI1_IO2_PB9: U2.B6(PB9) ; port QSPI1_IO2_PB9
QSPI1_IO3_PB10: U2.G6(PB10) ; port QSPI1_IO3_PB10
QSPI1_SCK_PB5: U2.A7(PB5) ; port QSPI1_SCK_PB5
RTC_OUT_PB13: U2.C4(PB13) ; port RTC_OUT_PB13
RTS_WILC_PA25: U2.W18(PA25) ; port RTS_WILC_PA25
RXD: U2.R1(RXD) ; port RXD
RXD_WILC_PA24: U2.W17(PA24) ; port RXD_WILC_PA24
SDIO_CLK_WILC_PA22: U2.V17(PA22) ; port SDIO_CLK_WILC_PA22
SDIO_CMD_WILC_PA28: U2.U13(PA28) ; port SDIO_CMD_WILC_PA28
SDIO_DAT0_WILC_PA18: U2.V19(PA18) ; port SDIO_DAT0_WILC_PA18
SDIO_DAT1_WILC_PA19: U2.V15(PA19) ; port SDIO_DAT1_WILC_PA19
SDIO_DAT2_WILC_PA20: U2.T10(PA20) ; port SDIO_DAT2_WILC_PA20
SDIO_DAT3_WILC_PA21: U2.U19(PA21) ; port SDIO_DAT3_WILC_PA21
SHDN: U2.P4(SHDN) ; port SHDN
TWCK_ECC608_PD22: U2.N6(PD22) ; port TWCK_ECC608_PD22
TWCK_MCP16502_PD20: R16.2 ; port TWCK_MCP16502_PD20
TWCK_SOM_PD20: R18.2 ; port TWCK_SOM_PD20
TWD_ECC608_PD21: U2.P3(PD21) ; port TWD_ECC608_PD21
TWD_MCP16502_PD19: R15.2 ; port TWD_MCP16502_PD19
TWD_SOM_PD19: R17.2 ; port TWD_SOM_PD19
TXD_WILC_PA23: U2.U18(PA23) ; port TXD_WILC_PA23
USBA_N: U2.V7(HHSDMA) ; port USBA_N
USBA_P: U2.W7(HHSDPA) ; port USBA_P
USBB_N: U2.V8(HHSDMB) ; port USBB_N
USBB_P: U2.W8(HHSDPB) ; port USBB_P
WKUP: U2.U2(WKUP) ; port WKUP
XIN_24MHz: U2.W5(XIN) Y2.3(OUT)
XIN_32KHz: C18.2 U2.U1(XIN32) Y1.1(Osc1)
XOUT_24MHz: R60.1 U2.W4(XOUT)
XOUT_32KHz: C19.2 U2.T1(XOUT32) Y1.2(Osc2)
NetC17_2: C17.2 R12.2 U2.V6(VBG)
NetR11_2: R11.2 U2.T2(TST)
NetR19_1: R19.1 U2.C19(ZQ)
NetR59_1: R59.1 U2.W11(PA0)

Not connected (* = marked no-connect by the designer): U2 T3(JTAGSEL)*

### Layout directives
differential pair; differential pair class DIFF90; net class DIFF90; rule Matched Net Lengths [Tolerance = 0.1mm]: USBA_N, USBA_P, USBB_N, USBB_P
mark named USB_MPU: (no net found under the mark)
net class SDMMC0: (no net found under the mark)

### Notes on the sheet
- SAMA5D2 MPU with 2Gb LPDDR2 x32 BGA-361
- 50Ω ± 10% single-ended trace impedance
- 100 MHz
- 90Ω ±10% differential trace impedance
  Routing top or bottom
- (near R59) CLK
- (near R59) CMD
- (near R59) DAT0
- (near R59) DAT1
- DAT2
- DAT3
- DAT4
- DAT5
- DAT6
- DAT7

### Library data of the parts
?#3 = Title Block A3
C17 = CAP1453: Capacitor; Manufacturer 1: TDK Corporation; Manufacturer Part Number 1: C0603C0G1E100D030BA; Description_: CAP CER 10pF 25V 0.5pF C0G SMD 0201; Dev Tools Status: Design; Tolerance: 0.5pF; Temperature Coeffcient: C0G; Type: Ceramic; Owner: Gabor Bihari; Populated: DNP
C18 C19 = CAP1996: Capacitor; Manufacturer 1: TDK Corporation; Manufacturer Part Number 1: CGA1A2C0G1H080D030BA; Description_: CAP CER 8pF 50V +/- 0.1pF C0G 0201; Dev Tools Status: Design; Tolerance: 0.1pF; Temperature Coeffcient: C0G; Type: Ceramic; Owner: Dragos Danaila; Populated: YES
C20-C23 C25 C64 C65 C82 C100 C101 = CAP1684: Capacitor; Manufacturer 1: TDK Corporation; Manufacturer Part Number 1: C1005X5R1A475K050BC; Voltage: 10V; Description_: CAP CER 4.7uF 10V 10% X5R SMD 0402; Dev Tools Status: Production; Tolerance: 10%; Temperature Coeffcient: X5R; Type: Ceramic; Owner: Jesus Aviles; Populated: YES
C24 C26-C37 C39-C63 C66-C81 C83 = CAP2003: Capacitor; Manufacturer 1: KEMET; Manufacturer Part Number 1: C0201C104K9PACTU; Voltage: 6.3V; Description_: CAP CER 0.1uF 6.3V 10% X5R 0201; Dev Tools Status: Design; Tolerance: 10%; Temperature Coeffcient: X5R; Owner: Dragos Danaila; Populated: YES; ESR: 0.005R; Type: Ceramic
C38 = CAP2003: as C11 on sheet 01 - Power
C99 = CAP1684: as C1 on sheet 01 - Power
C107 = CAP1201: Capacitor; Manufacturer 1: Murata; Manufacturer Part Number 1: GRM033R61A103KA01D; Voltage: 10V; Description_: CAP CER 10000pF 10V 10% X5R SMD 0201; Dev Tools Status: Production; Tolerance: 10%; Temperature Coeffcient: X5R; Type: Ceramic; Owner: Tad Ahlvers; Populated: YES
R11 = RSMT1252: as R2 on sheet 01 - Power
R12 = RES2053: Manufacturer 1: Yageo; Manufacturer Part Number 1: RC0201FR-075K62L; Description_: RES TKF 5.62K 1% 1/20W SMD 0201; Dev Tools Status: Design; Temperature Coeffcient: 200ppm/C; Power: 1/20W; Owner: Ilie Galan; Populated: YES
R13 R14 = RSMT1251: Manufacturer 1: Vishay Dale; Manufacturer Part Number 1: CRCW02012K20FKED; Description_: RES TKF 2.2K 1/20W SMD 0201; Dev Tools Status: Design; Voltage: 25V; Temperature Coeffcient: 100ppm/C; Current: 0.5A; Power: 1/20W; Owner: Dragos Danaila; Populated: YES
R15-R18 R59 = RES1473: Manufacturer 1: Panasonic Electronic Components; Manufacturer Part Number 1: ERJ-1GEF22R0C; Tolerance: 1%; Description_: RES TKF 22R 1% 1/20W SMD 0201; Dev Tools Status: Design; Voltage: 25V; Power: 1/20W; Owner: Mike Ragsdale; Populated: YES
R19 = RSMT1249: Manufacturer 1: Yageo; Manufacturer Part Number 1: RC0201FR-07240RL; Description_: RES TKF 240R 1/20W SMD 0201; Dev Tools Status: Design; Voltage: 25V; Temperature Coeffcient: 200ppm; Current: 0.5A; Power: 1/20W; Owner: Dragos Danaila; Populated: YES
R60 = RSMT1240: as R58 on sheet 01 - Power
U2 = MIC8130: SAMA5D2 MPU with 2Gb LPDDR2 x32 TFBGA-361; Manufacturer 1: Microchip Technology / Atmel; Manufacturer Part Number 1: ATSAMA5D27C-LD2G-CU; Value: SAMA5D2-LPDDR2-SIP-BGA-361; Description_: MCHP MCU SiP 32-BIT 500MHz 160kB 128kB 2Gbit ATSAMA5D27C-LD2G-CU 361-TFBGA; MAPS Description: CORTEX-A5 MPU,BGA,IND TEMP,2Gb LPDDR2, MRLC; Dev Tools Status: Design; Owner: Dragos Danaila; MPC: 3410H7DYBR01; LeadContent: Pb-FREE; TempRange: -40C to +85C; Stage: REL; PackageWidth: 16x16x1.2mm; PackingMedia: TRAY; ForceMinOrderQtyMult: True; MinOrderQty: 84; LeadCount: 361; Program Memory KBytes: 0; Ram: 131072; IOPins: 128; MaxSpeed: 500; OscillatorMHz: 32kHz, 12MHz; ADC Channels: 12; USART: 10; SPI: 7; CAN: 2; USBChannels: 3; Input Capture: 6; mtrlcntrlpwmchannels: 8; DigitalTimerQty_16bit: 4; Populated: YES
Y1 = OSC1206: Crystal; Manufacturer 1: NDK America, Inc.; Manufacturer Part Number 1: NX2012SA-32.768KHZ-EXS00A-MU00626; Description_: CRYSTAL 32.768kHz 6pF SMD NX2012SA-32.768KHZ-EXS00A-MU00626; Dev Tools Status: Design; Owner: Dragos Danaila; Tolerance: 20 ppm; Populated: YES
Y2 = MIC8647: Manufacturer 1: Microchip Technology; Description_: OSCILLATOR MEMS 24MHz DSC6003HI2B-024.0000 SMD VFLGA-4; Dev Tools Status: Design; Value: DSC6003HI2B-024.0000; Owner: Dragos Danaila; Populated: YES

## Sheet 03 - Ethernet.SchDoc
size B; CompanyName: Microchip Technology Inc.; Organization: Microchip Technology; Address1: 2355 West Chandler Blvd.; Address2: Chandler, AZ  85224; Address4: USA; SheetNumber: 4; SheetTotal: 6; SheetTitle: Ethernet
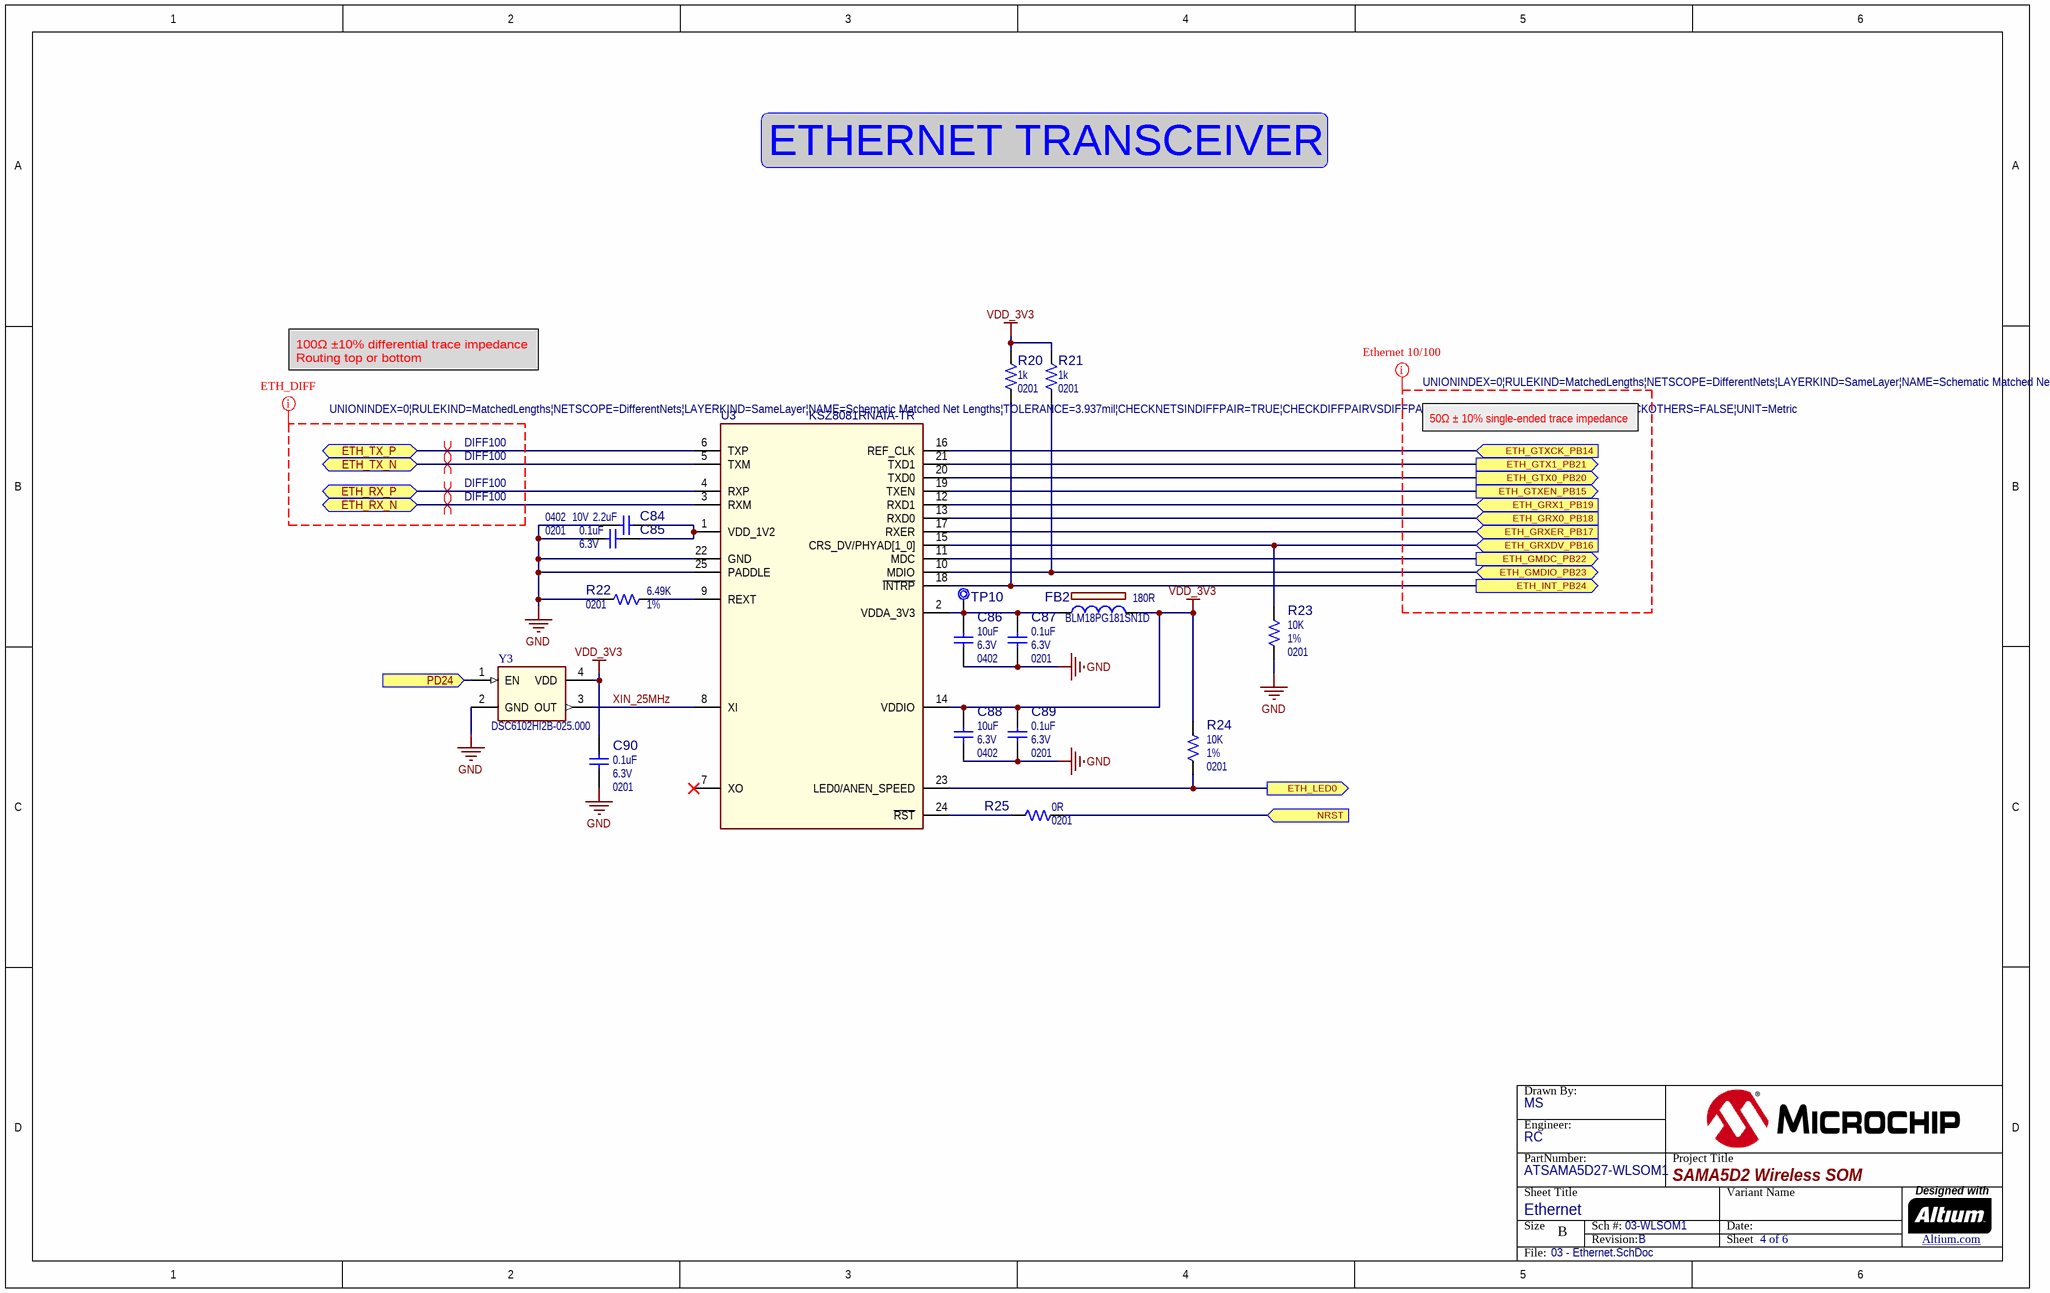
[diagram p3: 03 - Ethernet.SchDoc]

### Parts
(Parts that share a designator on the sheet are numbered #1, #2 ... from top to bottom, then left to right.)
?#4  (no value)  (graphical)
C84  value 2.2uF  Voltage: 10V  Package: 0402  [CAP_C_0402]  (hidden comment: Capacitor NP)
C85  value 0.1uF  Voltage: 6.3V  Package: 0201  [CAP_C_0201]  (hidden comment: Capacitor NP)
C86  value 10uF  Voltage: 6.3V  Package: 0402  [CAP_C_0402]  (hidden comment: Capacitor NP)
C87  value 0.1uF  Voltage: 6.3V  Package: 0201  [CAP_C_0201]  (hidden comment: Capacitor NP)
C88  value 10uF  Voltage: 6.3V  Package: 0402  [CAP_C_0402]  (hidden comment: Capacitor NP)
C89  value 0.1uF  Voltage: 6.3V  Package: 0201  [CAP_C_0201]  (hidden comment: Capacitor NP)
C90  value 0.1uF  Voltage: 6.3V  Package: 0201  [CAP_C_0201]  (hidden comment: Capacitor NP)
FB2  value 180R  Manufacturer Part Number 1: BLM18PG181SN1D  [IND_C_0603]  (hidden comment: Ferrite Bead)
R20  value 1k  Package: 0201  [RES_C_0201]  (hidden comment: Resistor)
R21  value 1k  Package: 0201  [RES_C_0201]  (hidden comment: Resistor)
R22  value 6.49K  Package: 0201  Tolerance: 1%  [RES_C_0201]  (hidden comment: Resistor)
R23  value 10K  Package: 0201  Tolerance: 1%  [RES_C_0201]  (hidden comment: Resistor)
R24  value 10K  Package: 0201  Tolerance: 1%  [RES_C_0201]  (hidden comment: Resistor)
R25  value 0R  Package: 0201  [RES_C_0201]  (hidden comment: Resistor)
TP10  Test Point No BOM  [TP_1mm_SMD]  (value not drawn)  (no BOM)
U3  value KSZ8081RNAIA-TR  [QFN-24_4X4]  (hidden comment: ETHERNET QFN-24)
Y3  Supplier Part Number 1: DSC6102HI2B-025.000  [DFN-4_VFLGA_1.6 X 1.2]  (hidden comment: OSCILLATOR 4 Pins)

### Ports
ETH_GMDC_PB22 (out), ETH_GMDIO_PB23 (bidir), ETH_GRX0_PB18 (in), ETH_GRX1_PB19 (in), ETH_GRXDV_PB16 (in), ETH_GRXER_PB17 (in), ETH_GTX0_PB20 (out), ETH_GTX1_PB21 (out), ETH_GTXCK_PB14 (in), ETH_GTXEN_PB15 (out), ETH_INT_PB24 (out), ETH_LED0 (out), ETH_RX_N (bidir), ETH_RX_P (bidir), ETH_TX_N (bidir), ETH_TX_P (bidir), NRST (in), PD24 (in)

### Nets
GND: C84.2 C85.2 C86.1 C87.1 C88.1 C89.1 C90.1 R22.1 R23.1 U3.22(GND) U3.25(PADDLE) Y3.2(GND)
VDD_3V3: C88.2 C89.2 C90.2 FB2.2 R20.2 R21.2 R24.2 U3.14(VDDIO) Y3.4(VDD)
ETH_GMDC_PB22: U3.11(MDC) ; port ETH_GMDC_PB22
ETH_GMDIO_PB23: R21.1 U3.10(MDIO) ; port ETH_GMDIO_PB23
ETH_GRX0_PB18: U3.13(RXD0) ; port ETH_GRX0_PB18
ETH_GRX1_PB19: U3.12(RXD1) ; port ETH_GRX1_PB19
ETH_GRXDV_PB16: R23.2 U3.15(CRS_DV/PHYAD[1_0]) ; port ETH_GRXDV_PB16
ETH_GRXER_PB17: U3.17(RXER) ; port ETH_GRXER_PB17
ETH_GTX0_PB20: U3.20(TXD0) ; port ETH_GTX0_PB20
ETH_GTX1_PB21: U3.21(TXD1) ; port ETH_GTX1_PB21
ETH_GTXCK_PB14: U3.16(REF_CLK) ; port ETH_GTXCK_PB14
ETH_GTXEN_PB15: U3.19(TXEN) ; port ETH_GTXEN_PB15
ETH_INT_PB24: R20.1 U3.18(~{INTRP}) ; port ETH_INT_PB24
ETH_LED0: R24.1 U3.23(LED0/ANEN_SPEED) ; port ETH_LED0
ETH_RX_N: U3.3(RXM) ; port ETH_RX_N
ETH_RX_P: U3.4(RXP) ; port ETH_RX_P
ETH_TX_N: U3.5(TXM) ; port ETH_TX_N
ETH_TX_P: U3.6(TXP) ; port ETH_TX_P
NRST: R25.1 ; port NRST
PD24: Y3.1(EN) ; port PD24
XIN_25MHz: U3.8(XI) Y3.3(OUT)
NetC84_1: C84.1 C85.1 U3.1(VDD_1V2)
NetC86_2: C86.2 C87.2 FB2.1 TP10.1 U3.2(VDDA_3V3)
NetR22_2: R22.2 U3.9(REXT)
NetR25_2: R25.2 U3.24(~{RST})

Not connected (* = marked no-connect by the designer): U3 7(XO)*

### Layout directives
net class ETH-PHY; rule Matched Net Lengths [Tolerance = 0.25mm]: (no net found under the mark)
mark named ETH_DIFF: (no net found under the mark)
differential pair; differential pair class DIFF100; net class DIFF100; rule Matched Net Lengths [Tolerance = 0.1mm]: ETH_RX_N, ETH_RX_P, ETH_TX_N, ETH_TX_P

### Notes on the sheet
- ETHERNET TRANSCEIVER
- 100Ω ±10% differential trace impedance
  Routing top or bottom
- 50Ω ± 10% single-ended trace impedance

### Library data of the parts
?#4 = Title Block B
C84 = CAP1468: Capacitor; Manufacturer 1: TDK Corporation; Manufacturer Part Number 1: C1005X7S1A225K050BC; Description_: CAP CER 2.2uF 10V 10% X7S SMD 0402; Dev Tools Status: Production; Tolerance: 10%; Temperature Coeffcient: X7S; Type: Ceramic; Owner: Sorin Stanoaia; Populated: YES
C85 C87 C89 C90 = CAP2003: as C11 on sheet 01 - Power
C86 C88 = CAP1766: Capacitor; Manufacturer 1: Yageo; Manufacturer Part Number 1: CC0402MRX5R5BB106; Description_: CAP CER 10uF 6.3V 20% X5R SMD 0402; Dev Tools Status: Design; Tolerance: 20%; Temperature Coeffcient: X5R; Type: Ceramic; Owner: Sam Charles; Populated: YES
FB2 = IND1453: Manufacturer 1: Murata Electronics North America; Description_: FERRITE 180R 1.5A SMD 0603; Dev Tools Status: Design; Owner: Dragos Danaila; DCR: 0.09R; Saturation Current: 1.5A; Test Frequency: 100MHz; Populated: YES
R20 R21 = RES1588: Manufacturer 1: Panasonic Electronic Components; Manufacturer Part Number 1: ERJ-1GEF1001C; Tolerance: 1%; Description_: RES TKF 1k 1% 1/20W SMD 0201; Dev Tools Status: Design; Voltage: 25V; Power: 1/20W; Owner: Gabor Bihari; Populated: YES
R22 = RSMT1250: Manufacturer 1: Yageo; Manufacturer Part Number 1: AC0201FR-076K49L; Description_: RES TKF 6.49K 1% 1/20W SMD 0201; Dev Tools Status: Design; Voltage: 25V; Temperature Coeffcient: 200ppm; Current: 0.5A; Power: 1/20W; Owner: Dragos Danaila; Populated: YES
R23 R24 = RSMT1252: as R2 on sheet 01 - Power
R25 = RSMT1240: as R5 on sheet 01 - Power
TP10 = CON1759: as TP1 on sheet 01 - Power
U3 = MIC7404: Manufacturer 1: Microchip Technology; Description_: MCHP INTERFACE ETHERNET KSZ8081RNAIA-TR QFN-24; Dev Tools Status: Design; Owner: Ciprian Abramov; Populated: YES
Y3 = MIC8785: Manufacturer 1: Microchip Technology Inc; Description_: OSCILLATOR MEMS 25MHz DSC6102HI2B-025.000 SMD VFLGA-4; Dev Tools Status: Design; Value: DSC6102HI2B-025.000; Owner: Dragos Danaila; Populated: YES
